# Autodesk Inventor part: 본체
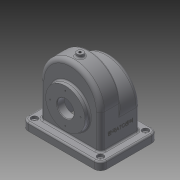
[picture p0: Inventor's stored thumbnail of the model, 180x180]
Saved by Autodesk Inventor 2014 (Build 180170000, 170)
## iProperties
Created: 2017-11
Part Number: 본체
Material: 일반
Document SubType Name: Modeling
Designer: net
Density: 1 g/cm^3
Appearance: 기본값
Author: net
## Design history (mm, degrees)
sketch "스케치1"
  geometry: L1 (0, 0)-(150, 0); L2 (150, 0)-(150, 15); L3 (150, 15)-(0, 15); L4 (0, 15)-(0, 0); L5 (17, 80)-(17, 15); L6 (133, 80)-(133, 15); A1 r 58 centre (75, 80) between (133, 80) and (17, 80); A2 r 58 centre (75, 57) between (133, 57) and (17, 57); 2 further points
  constraints: 12 end point, 4 point on circle, 4 point on line, 3 perpendicular, 2 centre point, 2 midpoint, 2 parallel, 2 tangent, 2 vertical alignment, 1 horizontal
  dimensions: "d0" = 150 distance of L3.end L2.end; "d1" = 15 distance of L2.end L1.end; "d2" = 116 diameter of A1; "d3" = 80 distance from line of L1 A1.centre; "d4" = 116 diameter of A2; "d5" = 57 distance from line of L1 A2.centre
extrude "돌출1" new body sketch "스케치1" stored distance "d6" = 110; taper "d7" = 0 deg
extrude "돌출2" join sketch "스케치1" distance "d8" = 38; taper "d9" = 0 deg
extrude "돌출3" join sketch "스케치1" distance "d10" = 38; taper "d11" = 0 deg
sketch "스케치2"
  geometry: L1 (17, 80)-(17, 15) reference; L2 (133, 15)-(17, 15) reference; L3 (133, 15)-(133, 80) reference; A1 r 58 centre (75, 80) between (133, 80) and (17, 80) reference; 1 further point
feature "쉘1" dims "d12" = 5
sketch "스케치3"
  geometry: L1 (5, -5)-(145, -5) reference; L2 (145, -5)-(145, -105) reference; L3 (5, -5)-(145, -5); L4 (145, -5)-(145, -105); L5 (145, -105)-(5, -105); L6 (5, -105)-(5, -5); L7 (133, -17)-(17, -17) reference; L8 (22, -22)-(22, -88) reference; L9 (5, -105)-(5, -5) reference; L10 (5, -105)-(145, -105) reference; L11 (145, -105)-(145, -5) reference; L12 (145, -5)-(5, -5) reference; L13 (22, -22)-(22, -88) reference; L14 (128, -22)-(22, -22) reference; L15 (128, -88)-(128, -22) reference; L16 (22, -88)-(128, -88) reference; L17 (22, -22)-(128, -22); L18 (128, -22)-(128, -88); L19 (128, -88)-(22, -88); L20 (22, -88)-(22, -22); 1 further point
  constraints: 16 end point, 4 parallel, 2 horizontal, 2 perpendicular
extrude "돌출4" join sketch "스케치3" distance "d13" = 10; taper "d14" = 0 deg
sketch "스케치4"
  geometry: L1 (0, 0)-(150, 0) reference; C1 r 37.5 at (75, 65); 1 further point
  constraints: 1 centre point, 1 midpoint, 1 vertical alignment
  dimensions: "d15" = 75 diameter of C1; "d16" = 65 distance from line of L1 C1.centre
extrude "돌출5" join sketch "스케치4" distance "d17" = 9; taper "d18" = 0 deg
sketch "스케치5"
  geometry: L1 (-150, 0)-(0, 0) reference; C1 r 31 at (-75, 65); 1 further point
  constraints: 1 centre point, 1 midpoint, 1 vertical alignment
  dimensions: "d19" = 62 diameter of C1; "d20" = 65 distance from line of L1 C1.centre
extrude "돌출6" join sketch "스케치5" distance "d21" = 10; taper "d22" = 0 deg
sketch "스케치6"
  geometry: C1 r 31 at (0, 0) reference; C2 r 16 at (0, 0); 1 further point
  constraints: 1 centre point, 1 coincident
  dimensions: "d23" = 32 diameter of C2
extrude "돌출7" cut sketch "스케치6" stored distance "d24" = 10; taper "d25" = 0 deg
sketch "스케치7"
  geometry: C1 r 16 at (0, 0) reference; 2 further points
  constraints: 1 vertical alignment
  dimensions: "d26" = 26 distance of C1.centre point (0, 26)
hole "구멍1" sketch "스케치7" at (0, 26) diameter "d27" = 2.459; stored, may be unused: countersink angle "d31" = 90 deg, drill point angle "d33" = 118 deg; dims "d28" = 6, "d29" = 4, "d30" = 2, "d32" = 8
sketch "스케치8"
  geometry: C1 r 16 at (0, 0) reference; 2 further points
  constraints: 1 vertical alignment
  dimensions: "d37" = 29 distance of C1.centre point (0, 29)
hole "구멍2" sketch "스케치8" at (0, 29) diameter "d38" = 2.459; stored, may be unused: countersink angle "d42" = 90 deg, drill point angle "d44" = 118 deg; dims "d39" = 6, "d40" = 4, "d41" = 2, "d43" = 8
fillet "모깎기1" dims "d48" = 12
sketch "스케치10"
  geometry: A1 r 12 centre (0, 12) between (-12, 12) and (0, 0) reference; A2 r 12 centre (126, 12) between (126, 0) and (138, 12) reference; A3 r 12 centre (126, 98) between (138, 98) and (126, 110) reference; A4 r 12 centre (0, 98) between (0, 110) and (-12, 98) reference; 5 further points
  constraints: 4 coincident
hole "구멍3" sketch "스케치10" at (0, 98), (0, 12), (126, 12), (126, 98) diameter "d49" = 5; stored, may be unused: countersink angle "d53" = 90 deg, drill point angle "d55" = 118 deg; dims "d50" = 6, "d51" = 12, "d52" = 5, "d54" = 8
node "작업 평면1"
sketch "스케치11"
  geometry: L1 (-58, 0)-(58, 0) reference; L2 (58, 0)-(58, 38) reference; L3 (-58, 38)-(58, 38) reference; L4 (-58, 0)-(-58, 38) reference; C1 r 6 at (0, 19); 2 further points
  constraints: 1 centre point, 1 midpoint, 1 vertical alignment
  dimensions: "d56" = 12 diameter of C1; "d57" = 19 distance from line of C1.centre L3
extrude "돌출8" join sketch "스케치11" distance "d58" = 6; taper "d60" = 0 deg; dims "d59" = 5, "d61" = 0
hole "구멍4" diameter "d64" = 4.459; stored, may be unused: countersink angle "d68" = 90 deg, drill point angle "d70" = 118 deg; dims "d65" = 6, "d66" = 12, "d67" = 5, "d69" = 8, "d71" = 10, "d72" = 10
chamfer "모따기1" distance "d73" = 1; stored, may be unused: second distance "d74" = 2, angle "d75" = 45 deg
fillet "모깎기2" dims "d76" = 3, "d77" = 3, "d78" = 3
fillet "모깎기3" dims "d79" = 8
fillet "모깎기4" dims "d80" = 3
sketch "스케치12"
  geometry: L1 (73, -18)-(-13, -18) reference; 3 further points
  constraints: 1 midpoint, 1 vertical alignment, 1 other
  dimensions: "d81" = 40 distance from line of L1 point (30, 22)
feature "엠보싱1" sketch "스케치12" dims "d0" = 150, "d1" = 15, "d2" = 116, "d3" = 80, "d4" = 116, "d5" = 57, "d82" = 0.5, "d83" = 0
node "솔리드1"
pattern_circular "원형 패턴1" dims angle "d35" = 360 deg
pattern_circular "원형 패턴2" dims angle "d46" = 360 deg
node "투영된 루프1"
node "투영된 루프2"
